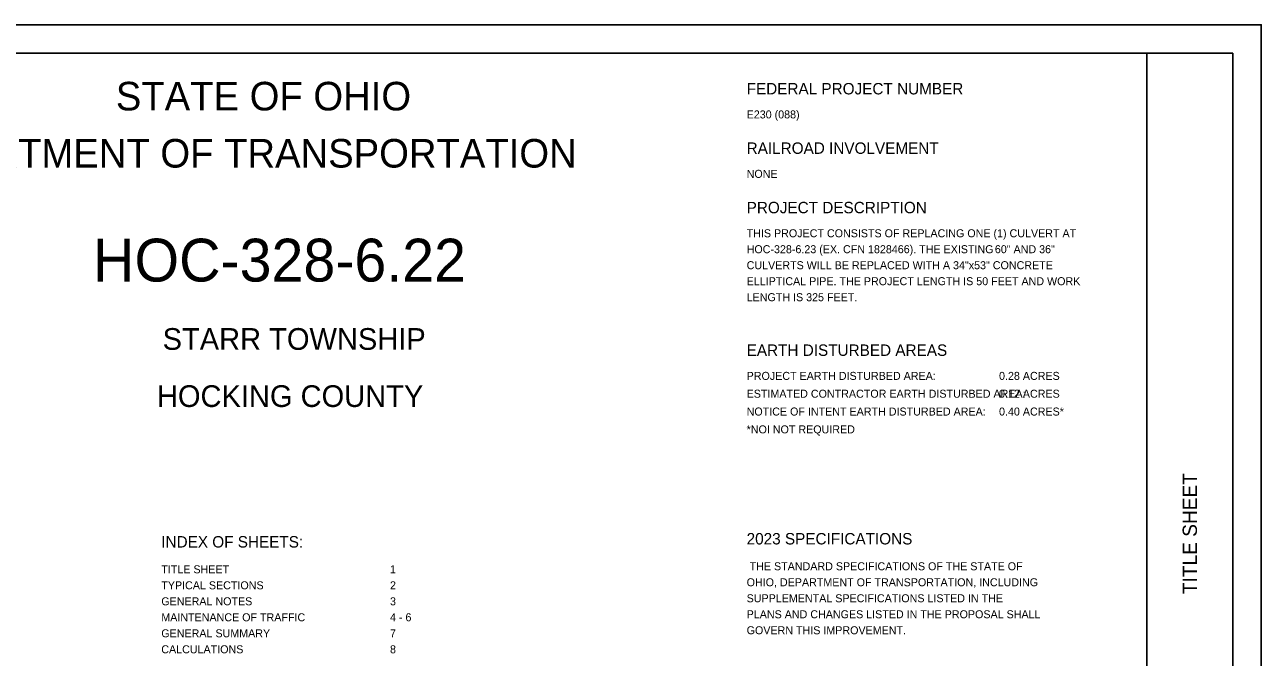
# Model space of a CAD drawing. Extents: x 0 to 34, y 0 to 22.
# Drawn here: x 12.37 to 34, y 10.93 to 22 of the extents above; entities that cross this region are included whole.
import ezdxf

# ---------------------------------------------------------------- set-up
doc = ezdxf.new("R2010")
doc.units = 0
for name, color, linetype in [('SH_Border', 7, 'Continuous'), ('SH_Cut_Line', 7, 'Continuous'), ('SH_Data', 7, 'Continuous'), ('SH_Text', 7, 'Continuous')]:
    doc.layers.add(name, color=color, linetype=linetype)

msp = doc.modelspace()

# ---------------------------------------------------------------- linework, layer by layer
at = {"layer": 'SH_Border'}
msp.add_line((32, 0.5), (32, 21.5), dxfattribs=at)
msp.add_lwpolyline([(1.5, 21.5), (33.5, 21.5), (33.5, 0.5), (1.5, 0.5)], close=True, dxfattribs=at)
at = {"layer": 'SH_Cut_Line'}
msp.add_lwpolyline([(0, 0), (34, 0), (34, 22), (0, 22)], close=True, dxfattribs=at)

# ---------------------------------------------------------------- texts
at = {"layer": 'SH_Data'}
msp.add_text('TITLE SHEET', height=0.25, rotation=90, dxfattribs=at).set_placement((32.875, 12.035))
at = {"layer": 'SH_Text'}
for s, height, p in [('STATE OF OHIO', 0.5, (13.968, 20.5)), ('FEDERAL PROJECT NUMBER', 0.2, (25, 20.78)), ('E230 (088)', 0.14, (25, 20.36)), ('DEPARTMENT OF TRANSPORTATION', 0.5, (9.955, 19.5)), ('RAILROAD INVOLVEMENT', 0.2, (25, 19.74)), ('NONE', 0.14, (25, 19.32)), ('PROJECT DESCRIPTION', 0.2, (25, 18.7)), ('THIS PROJECT CONSISTS OF REPLACING ONE (1) CULVERT AT ', 0.14, (25, 18.28)), ('HOC-328-6.22', 0.75, (13.57, 17.505)), ('HOC-328-6.23 (EX. CFN 1828466). THE EXISTING', 0.14, (25, 18.001)), (' 60" AND 36" ', 0.14, (29.289, 18.001)), ('CULVERTS WILL BE REPLACED WITH A 34"x53" CONCRETE ', 0.14, (25, 17.721)), ('ELLIPTICAL PIPE. THE PROJECT LENGTH IS 50 FEET AND WORK ', 0.14, (25, 17.441)), ('LENGTH IS 325 FEET.', 0.14, (25, 17.161)), ('STARR TOWNSHIP', 0.38, (14.786, 16.31)), ('EARTH DISTURBED AREAS', 0.2, (25, 16.204)), ('PROJECT EARTH DISTURBED AREA:', 0.14, (25, 15.784)), ('0.28 ACRES', 0.14, (29.414, 15.784)), ('HOCKING COUNTY', 0.38, (14.687, 15.31)), ('ESTIMATED CONTRACTOR EARTH DISTURBED AREA:', 0.14, (25, 15.472)), ('0.12 ACRES', 0.14, (29.414, 15.472)), ('NOTICE OF INTENT EARTH DISTURBED AREA:', 0.14, (25, 15.16)), ('0.40 ACRES*', 0.14, (29.414, 15.16)), ('*NOI NOT REQUIRED', 0.14, (25, 14.848)), ('INDEX OF SHEETS:', 0.2, (14.763, 12.85)), ('2023 SPECIFICATIONS', 0.2, (25, 12.904)), (' THE STANDARD SPECIFICATIONS OF THE STATE OF', 0.14, (25, 12.452)), ('TITLE SHEET', 0.14, (14.763, 12.399)), ('1', 0.14, (18.763, 12.399)), ('TYPICAL SECTIONS', 0.14, (14.763, 12.119)), ('2', 0.14, (18.763, 12.119)), ('OHIO, DEPARTMENT OF TRANSPORTATION, INCLUDING', 0.14, (25, 12.172)), ('GENERAL NOTES', 0.14, (14.763, 11.839)), ('3', 0.14, (18.763, 11.839)), ('SUPPLEMENTAL SPECIFICATIONS LISTED IN THE', 0.14, (25, 11.892)), ('MAINTENANCE OF TRAFFIC', 0.14, (14.763, 11.559)), ('4 - 6', 0.14, (18.763, 11.559)), ('PLANS AND CHANGES LISTED IN THE PROPOSAL SHALL', 0.14, (25, 11.612)), ('GOVERN THIS IMPROVEMENT.', 0.14, (25, 11.332)), ('GENERAL SUMMARY', 0.14, (14.763, 11.279)), ('7', 0.14, (18.763, 11.279)), ('CALCULATIONS', 0.14, (14.763, 10.999)), ('8', 0.14, (18.763, 10.999))]:
    msp.add_text(s, height=height, dxfattribs=at).set_placement(p)

doc.saveas('drawing.dxf')
